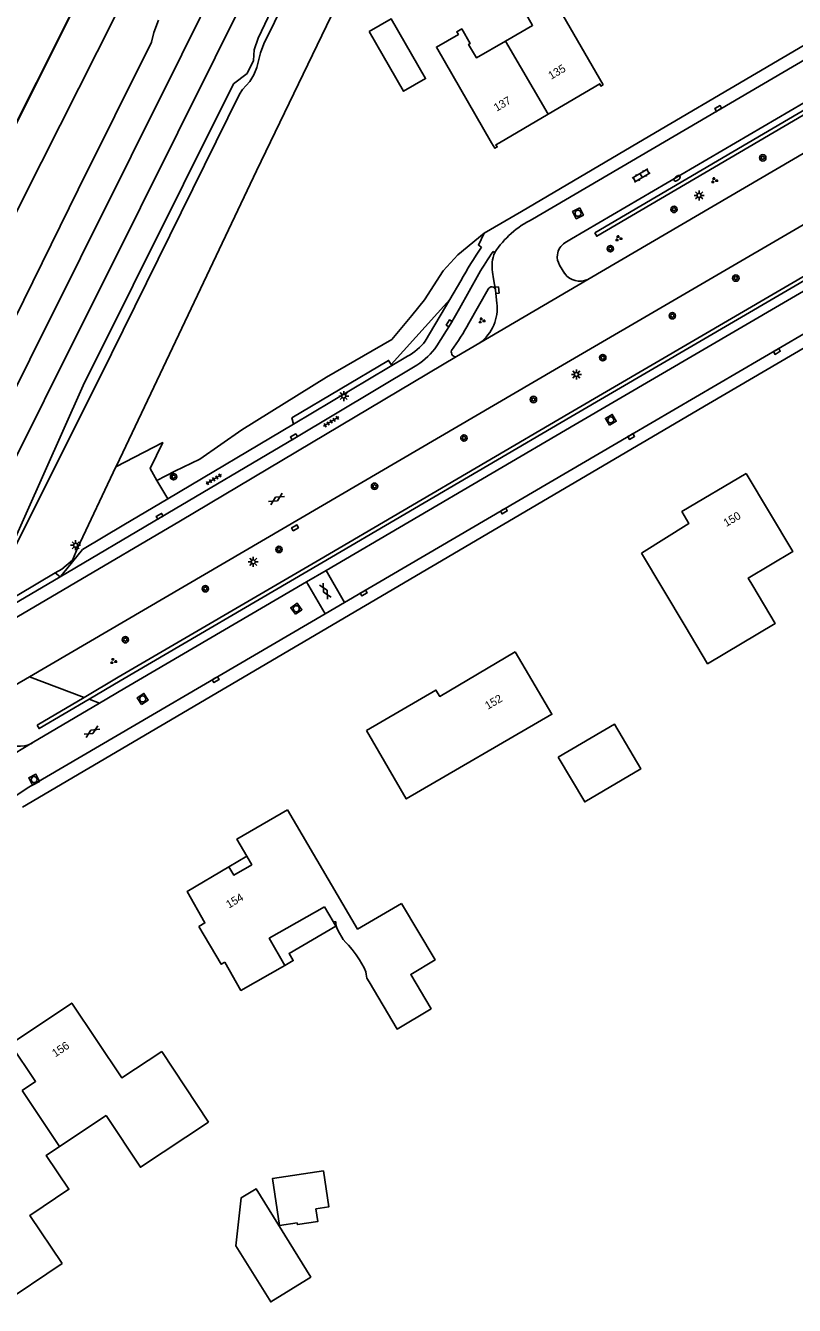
# Model space of a CAD drawing. Extents: x 135999 to 138000, y 396000 to 398501.
# Drawn here: x 136091.1 to 136187.2, y 397354.7 to 397514.6 of the extents above; entities that cross this region are included whole.
import ezdxf

# ---------------------------------------------------------------- set-up
doc = ezdxf.new("R2010")
doc.units = 0
for name, color, linetype in [('gg-afsc-hekwerk', 7, 'Continuous'), ('gg-anno-huisnummerreeks BGT', 7, 'Continuous'), ('gg-aspt-spoorlijn', 7, 'Continuous'), ('gg-bbg-gedigitaliseerde bebouwing', 7, 'Continuous'), ('gg-bbg-gedigitaliseerde bijgebouw', 7, 'Continuous'), ('gg-bbg-hoofdgebouw', 7, 'Continuous'), ('gg-bbg-luifel en loopbrug', 7, 'Continuous'), ('gg-bbg-tussenscheiding', 7, 'Continuous'), ('gg-knt-bovenkant onderkant talud', 7, 'Continuous'), ('gg-knt-verharding', 7, 'Continuous'), ('gt-grn-bladgrens', 7, 'Continuous'), ('gt-grn-groengrens', 7, 'Continuous'), ('gt-grn-vlakafsluiter', 7, 'Continuous'), ('gt-symb-boom', 7, 'Continuous'), ('gt-symb-brandkraan', 7, 'Continuous'), ('gt-symb-gesloten verharding', 7, 'Continuous'), ('gt-symb-groenvak', 7, 'Continuous'), ('gt-symb-klinker verharding', 7, 'Continuous'), ('gt-symb-kolk', 7, 'Continuous'), ('gt-symb-lichtmast', 7, 'Continuous'), ('gt-symb-rioolschacht', 7, 'Continuous'), ('gt-symb-tegel verharding', 7, 'Continuous'), ('gx-grn-maaiveld', 7, 'Continuous')]:
    doc.layers.add(name, color=color, linetype=linetype)

# ---------------------------------------------------------------- blocks, each defined once
blk = doc.blocks.new('gt0-KOLK')
at = {"layer": 'gt-symb-kolk'}
blk.add_lwpolyline([(0, 0), (0.38, 0), (0.38, 0.4), (-0.38, 0.4), (-0.38, 0), (0, 0)], dxfattribs=at)
blk = doc.blocks.new('gt0-BOOM')
at = {"layer": 'gt-symb-boom'}
for radius in [0.4, 0.2]:
    blk.add_circle((0, 0), radius, dxfattribs=at)
blk = doc.blocks.new('gt0-GRVAK')
at = {"layer": 'gt-symb-groenvak'}
for p, q in [((-0.11, 0.19), (-0.23, 0.24)), ((-0.18, 0.15), (0.09, 0.15)), ((-0.09, 0.21), (-0.16, 0.32)), ((-0.05, 0.21), (-0.05, 0.39)), ((0, 0.21), (0.06, 0.32)), ((0.02, 0.19), (0.13, 0.24)), ((0.26, -0.05), (0.2, 0.06)), ((0.3, -0.05), (0.3, 0.13)), ((0.35, -0.05), (0.41, 0.06)), ((-0.24, -0.23), (-0.36, -0.18)), ((-0.32, -0.26), (-0.05, -0.26)), ((-0.23, -0.21), (-0.29, -0.1)), ((-0.18, -0.2), (-0.18, -0.02)), ((-0.14, -0.21), (-0.07, -0.1)), ((-0.12, -0.23), (0, -0.18)), ((0.24, -0.07), (0.12, -0.02)), ((0.17, -0.11), (0.44, -0.11)), ((0.37, -0.07), (0.49, -0.02))]:
    blk.add_line(p, q, dxfattribs=at)
blk = doc.blocks.new('gt0-LMAST')
at = {"layer": 'gt-symb-lichtmast'}
for p, q in [((-0.18, 0.17), (-0.45, 0.44)), ((-0.01, 0.25), (-0.01, 0.62)), ((0.17, 0.17), (0.44, 0.44)), ((-0.26, 0), (-0.63, 0)), ((-0.18, -0.18), (-0.45, -0.45)), ((-0.01, -0.25), (-0.01, -0.63)), ((0.44, -0.45), (0.17, -0.18)), ((0.24, 0), (0.62, 0))]:
    blk.add_line(p, q, dxfattribs=at)
blk.add_circle((-0.01, 0), 0.25, dxfattribs=at)
blk = doc.blocks.new('gt0-TEG1')
at = {"layer": 'gt-symb-tegel verharding'}
for p, q in [((-1.12, 0), (1.13, 0)), ((-0.9, -0.25), (-0.9, 0.25)), ((-0.45, -0.25), (-0.45, 0.25)), ((0, -0.25), (0, 0.25)), ((0.45, -0.25), (0.45, 0.25)), ((0.9, -0.25), (0.9, 0.25))]:
    blk.add_line(p, q, dxfattribs=at)
blk = doc.blocks.new('gt0-GESVH1')
at = {"layer": 'gt-symb-gesloten verharding'}
for p, q in [((-0.99, -0.26), (0.01, 0.24)), ((0.01, -0.26), (-0.99, 0.24)), ((0.01, 0.24), (1.01, -0.26)), ((1.01, 0.24), (0.01, -0.26))]:
    blk.add_line(p, q, dxfattribs=at)
blk = doc.blocks.new('gt0-RS')
at = {"layer": 'gt-symb-rioolschacht'}
blk.add_lwpolyline([(-0.5, -0.5), (0.5, -0.5), (0.5, 0.5), (-0.5, 0.5)], close=True, dxfattribs=at)
blk.add_circle((0, 0), 0.375, dxfattribs=at)
blk = doc.blocks.new('gt0-KL1')
at = {"layer": 'gt-symb-klinker verharding'}
for p, q in [((-1.15, 0.3), (1.15, 0.3)), ((-1, -0.3), (-1, 0.3)), ((-0.5, 0.3), (-0.5, 0.45)), ((0, -0.3), (0, 0.3)), ((0.5, 0.3), (0.5, 0.45)), ((1, -0.3), (1, 0.3)), ((-1.15, -0.3), (1.15, -0.3)), ((-0.5, -0.45), (-0.5, -0.3)), ((0.5, -0.45), (0.5, -0.3))]:
    blk.add_line(p, q, dxfattribs=at)
blk = doc.blocks.new('gt0-BR')
at = {"layer": 'gt-symb-brandkraan'}
for centre, radius, start, end in [((-0.24, 0), 0.206, 107.5669, 252.4331), ((0.6, -2.66), 3, 106.892, 107.5669), ((0, -0.69), 0.938, 73.108, 106.892), ((-0.6, -2.66), 3, 72.4331, 73.108), ((0.24, 0), 0.206, 287.567, 72.4331), ((0.6, 2.66), 3, 252.4331, 253.108), ((0, 0.69), 0.938, 253.108, 286.8921), ((-0.6, 2.66), 3, 286.8921, 287.567)]:
    blk.add_arc(centre, radius, start, end, dxfattribs=at)

msp = doc.modelspace()

# ---------------------------------------------------------------- linework, layer by layer
at = {"layer": 'gg-afsc-hekwerk'}
msp.add_lwpolyline([(136206.22, 397710.07), (136203.26, 397711.27), (136196.98, 397710.23), (136193.86, 397709.75), (136188.71, 397699.53), (136178.32, 397679.53), (136172.59, 397668.77), (136160.48, 397645.24), (136132.77, 397588.81), (136102.14, 397526.87), (136090.23, 397502.97), (136088.59, 397499.81), (136086.91, 397496.59), (136075.23, 397472.87), (136076.15, 397472.41)], dxfattribs=at)
at = {"layer": 'gg-aspt-spoorlijn'}
for points in [[(136075.9, 397441.46), (136078.9, 397447.5), (136110.62, 397511), (136126.65, 397543.4), (136168.42, 397626.98), (136182.98, 397656.49), (136206.97, 397704.32), (136208.88, 397708.17)], [(136081.38, 397443.76), (136105.46, 397491.91), (136152.12, 397585.65), (136171.93, 397625.02), (136194.83, 397671.15), (136212.4, 397706.41)]]:
    msp.add_lwpolyline(points, dxfattribs=at)
at = {"layer": 'gg-bbg-gedigitaliseerde bebouwing'}
for p, q in [((136168.08, 397448.74), (136173.51, 397439.61)), ((136128.43, 397404.54), (136129.52, 397402.71)), ((136108.12, 397386.48), (136113.95, 397377.65)), ((136101.15, 397378.49), (136095.33, 397374.6)), ((136087.83, 397354.75), (136095.65, 397359.97))]:
    msp.add_line(p, q, dxfattribs=at)
for points in [[(136163.28, 397507.24), (136155.93, 397519.94), (136152.95, 397518.22), (136152.8, 397518.48), (136152.19, 397518.14), (136153.29, 397516.23), (136153.48, 397516.34), (136154.45, 397514.65), (136151.05, 397512.69)], [(136151.05, 397512.69), (136147.42, 397510.61), (136146.46, 397512.27), (136146.64, 397512.38), (136145.59, 397514.21), (136144.97, 397513.86), (136145.17, 397513.52), (136142.42, 397511.95), (136149.33, 397500)], [(136181.98, 397444.66), (136181.41, 397445.61), (136186.97, 397448.93), (136181.16, 397458.69)], [(136181.98, 397444.66), (136184.79, 397439.95), (136176.33, 397434.9), (136173.51, 397439.61)], [(136152.29, 397436.4), (136156.86, 397428.61), (136138.65, 397418.02), (136133.69, 397426.58)], [(136128.43, 397404.54), (136121.53, 397400.61), (136123.47, 397397.21)], [(136134.01, 397395.17), (136137.52, 397389.27), (136141.77, 397391.8), (136139.22, 397396.09), (136142.26, 397397.9), (136138.08, 397404.94)], [(136115.98, 397397.62), (136115.53, 397397.36), (136112.74, 397402.09)], [(136129.52, 397402.71), (136129.86, 397402.66), (136129.86, 397402.45), (136129.9, 397402.15), (136129.97, 397401.9), (136130.15, 397401.54), (136130.78, 397400.45), (136131.11, 397400.1), (136131.45, 397399.75), (136131.91, 397399.2), (136132.42, 397398.53), (136132.81, 397397.94), (136133.42, 397396.91), (136133.59, 397396.43), (136133.66, 397396.12), (136133.75, 397395.65), (136134.01, 397395.17)], [(136123.47, 397397.21), (136117.99, 397394.09), (136115.98, 397397.62)], [(136113.95, 397377.65), (136105.43, 397372.01), (136101.15, 397378.49)], [(136095.33, 397374.6), (136093.67, 397373.49), (136096.5, 397369.26), (136091.61, 397365.98), (136095.65, 397359.97)]]:
    msp.add_lwpolyline(points, dxfattribs=at)
at = {"layer": 'gg-bbg-gedigitaliseerde bijgebouw'}
for points in [[(136134.04, 397513.88), (136136.78, 397515.46), (136141.07, 397508.01), (136138.32, 397506.43), (136134.04, 397513.88)], [(136157.66, 397423.23), (136160.96, 397417.64), (136167.98, 397421.78), (136164.68, 397427.37), (136157.66, 397423.23)], [(136128.3, 397371.55), (136121.93, 397370.6), (136122.8, 397364.73), (136125.02, 397365.06), (136125.06, 397364.85), (136127.6, 397365.22), (136127.36, 397366.81), (136128.97, 397367.05), (136128.3, 397371.55)], [(136117.38, 397362.21), (136118.04, 397368.19), (136119.91, 397369.31), (136126.73, 397358.29), (136121.73, 397355.19), (136117.38, 397362.21)]]:
    msp.add_lwpolyline(points, dxfattribs=at)
at = {"layer": 'gg-bbg-hoofdgebouw'}
msp.add_line((136150.3, 397500), (136156.39, 397503.58), dxfattribs=at)
for points in [[(136156.39, 397503.58), (136162.84, 397507.36), (136162.98, 397507.08), (136163.28, 397507.24)], [(136149.33, 397500), (136149.74, 397499.3), (136150.04, 397499.48), (136149.87, 397499.75), (136150.3, 397500)], [(136181.16, 397458.69), (136173.12, 397453.91), (136174, 397452.43), (136168.08, 397448.74)], [(136133.69, 397426.58), (136142.37, 397431.61), (136142.84, 397430.82), (136152.29, 397436.4)], [(136123.82, 397416.65), (136117.5, 397413), (136118.73, 397410.87)], [(136138.08, 397404.94), (136132.57, 397401.77), (136123.82, 397416.65)], [(136116.49, 397409.54), (136117.09, 397408.5), (136119.35, 397409.8), (136118.73, 397410.87)], [(136116.49, 397409.54), (136111.27, 397406.44), (136113.5, 397402.53), (136112.74, 397402.09)], [(136090.67, 397381.61), (136092.33, 397382.73), (136089.21, 397387.4), (136096.86, 397392.51), (136103.12, 397383.16), (136108.12, 397386.48)]]:
    msp.add_lwpolyline(points, dxfattribs=at)
at = {"layer": 'gg-bbg-luifel en loopbrug'}
msp.add_line((136116.49, 397409.54), (136118.73, 397410.87), dxfattribs=at)
msp.add_lwpolyline([(136123.47, 397397.21), (136124.54, 397397.82), (136124.01, 397398.73), (136129.87, 397402.11), (136129.52, 397402.71)], dxfattribs=at)
at = {"layer": 'gg-bbg-tussenscheiding'}
for p, q in [((136151.05, 397512.69), (136156.39, 397503.58)), ((136090.67, 397381.61), (136095.33, 397374.6))]:
    msp.add_line(p, q, dxfattribs=at)
at = {"layer": 'gg-knt-bovenkant onderkant talud'}
msp.add_lwpolyline([(136096.95, 397447.84), (136097.55, 397449.34), (136102.37, 397459.52)], dxfattribs=at)
at = {"layer": 'gg-knt-verharding'}
for p, q in [((136149.72, 397486.27), (136149.52, 397486.41)), ((136158.47, 397483.64), (136157.83, 397484.71)), ((136144.12, 397480.42), (136145.5, 397482.75)), ((136147.85, 397475), (136161.34, 397482.9)), ((136141.02, 397475.22), (136144.12, 397480.42)), ((136146.49, 397477.45), (136148.89, 397481.71)), ((136149.99, 397479.97), (136149.82, 397481.59)), ((136144.96, 397473.29), (136147.85, 397475)), ((136138.83, 397473.34), (136124.55, 397464.85)), ((136124.55, 397464.85), (136108.84, 397455.51)), ((136094.79, 397446.25), (136095.62, 397446.74)), ((136095.62, 397446.74), (136096.95, 397447.84)), ((136095.69, 397446.12), (136095.42, 397445.78)), ((136128.65, 397446.57), (136126.2, 397445.14)), ((136126.2, 397445.14), (136128.51, 397441.15)), ((136130.94, 397442.57), (136128.65, 397446.57)), ((136130.94, 397442.57), (136128.51, 397441.15)), ((136086.85, 397430.54), (136091.55, 397433.29)), ((136100.33, 397429.99), (136091.89, 397425.01))]:
    msp.add_line(p, q, dxfattribs=at)
for points in [[(136154.43, 397490.43), (136206.35, 397520.89), (136227.04, 397533), (136240.35, 397540.82), (136259.46, 397552.07), (136276.59, 397562.11), (136287.32, 397568.41), (136289.03, 397569.4)], [(136289.47, 397564.17), (136255.15, 397544.03), (136190.06, 397506), (136159.32, 397487.99), (136158.49, 397487.49)], [(136161.34, 397482.9), (136241.87, 397530.06), (136295.03, 397560.71), (136295.87, 397561.3)], [(136091.55, 397433.29), (136157.18, 397471.63), (136241.16, 397520.6), (136300.13, 397555.2)], [(136302.91, 397548.5), (136285.12, 397538.12), (136201.43, 397489.11), (136159.77, 397464.79), (136128.65, 397446.57)], [(136307.8, 397544.23), (136276.31, 397525.85), (136176.45, 397467.39), (136090.68, 397416.98)], [(136130.94, 397442.57), (136166.67, 397463.47), (136201.88, 397484.04), (136272.38, 397525.34), (136305.21, 397544.51)], [(136196.49, 397516.94), (136168.4, 397500.43), (136153.05, 397491.42), (136148.38, 397488.72)], [(136148.38, 397488.72), (136147.69, 397487.22), (136148.08, 397486.96)], [(136142.48, 397474.62), (136144.2, 397477.33), (136144.81, 397478.41), (136145.3, 397479.28), (136147.74, 397483.63)], [(136149.45, 397483.84), (136149.57, 397483.01), (136149.82, 397481.59)], [(136144.96, 397473.29), (136110.46, 397452.75), (136082.67, 397436.44)], [(136139.98, 397472.21), (136124.72, 397463.09), (136107.95, 397453.16), (136095.42, 397445.78)], [(136108.84, 397455.51), (136103.38, 397452.26), (136098.21, 397449.2), (136095.69, 397446.12)], [(136095.42, 397445.78), (136089.53, 397442.32), (136084, 397439.1)], [(136084.66, 397440.42), (136085.44, 397440.71), (136094.79, 397446.25)], [(136126.2, 397445.14), (136103.48, 397431.84), (136100.33, 397429.99)], [(136128.51, 397441.15), (136091.47, 397419.47), (136089.79, 397418.36)], [(136086.89, 397421.92), (136088.61, 397423.04), (136091.89, 397425.01)]]:
    msp.add_lwpolyline(points, dxfattribs=at)
for centre, radius, start, end in [((136159.61, 397479.83), 11.81, 116.0465, 146.9071), ((136184.54, 397461.82), 44.3, 145.4133, 151.8034), ((136159.56, 397485.76), 2.02, 121.6775, 172.8362), ((136187.09, 397460.43), 45.68, 145.335, 149.4664), ((136154.02, 397484.57), 4.63, 158.4245, 189.1686), ((136159.55, 397485.77), 2.02, 172.8809, 211.4406), ((136160.37, 397485.07), 2.37, 216.823, 294.1108), ((136149.34, 397481.49), 0.497, 11.5836, 154.0001), ((136144.68, 397479.31), 5.35, 306.3606, 7.0975), ((136115.31, 397494.7), 35.63, 324.5449, 331.0477), ((136135.93, 397478.95), 6.31, 297.3096, 323.7941), ((136135.56, 397479.31), 8.36, 301.9139, 325.9199), ((136144.83, 397473.81), 0.541, 156.2874, 284.4686), ((136090.39, 397427.59), 2.99, 223.7791, 300.1932)]:
    msp.add_arc(centre, radius, start, end, dxfattribs=at)
at = {"layer": 'gt-grn-bladgrens'}
for p, q in [((136107.1, 397513.77), (136107.7, 397515.32)), ((136097.64, 397494.15), (136106.82, 397512.56)), ((136106.82, 397512.56), (136107.1, 397513.77)), ((136085.15, 397468.75), (136097.64, 397494.15))]:
    msp.add_line(p, q, dxfattribs=at)
at = {"layer": 'gt-grn-groengrens'}
for p, q in [((136108.84, 397455.51), (136107.5, 397457.81)), ((136091.55, 397433.29), (136098.41, 397430.71)), ((136098.41, 397430.71), (136092.51, 397427.24)), ((136099.01, 397430.48), (136100.33, 397429.99))]:
    msp.add_line(p, q, dxfattribs=at)
for points in [[(136289.46, 397563.39), (136289.71, 397562.96), (136162.46, 397488.32), (136162.21, 397488.75)], [(136289.46, 397563.39), (136181.39, 397500), (136162.21, 397488.75)], [(136301.08, 397549.28), (136284.32, 397539.51), (136200.63, 397490.5), (136158.97, 397466.18), (136127.84, 397447.95)], [(136301.08, 397549.28), (136301.33, 397548.85), (136284.57, 397539.07), (136200.88, 397490.07), (136159.22, 397465.74), (136128.09, 397447.52)], [(136148.38, 397488.72), (136145.11, 397486.01), (136143.27, 397483.99), (136140.96, 397480.36), (136139.34, 397478.42), (136136.86, 397475.43), (136128.7, 397470.69), (136118.13, 397464.14), (136112.84, 397460.46), (136109.72, 397458.98), (136107.5, 397457.81)], [(136124.55, 397464.85), (136124.37, 397465.65), (136136.46, 397472.8), (136136.77, 397472.31), (136144.12, 397480.42)], [(136107.5, 397457.81), (136106.64, 397459.3), (136108.23, 397462.54), (136102.37, 397459.52)], [(136127.84, 397447.95), (136102.67, 397433.22), (136098.41, 397430.71)], [(136128.09, 397447.52), (136102.92, 397432.79), (136099.01, 397430.48)], [(136099.01, 397430.48), (136092.77, 397426.81), (136092.51, 397427.24)]]:
    msp.add_lwpolyline(points, dxfattribs=at)
at = {"layer": 'gt-grn-vlakafsluiter'}
msp.add_line((136094.79, 397446.25), (136095.42, 397445.78), dxfattribs=at)
msp.add_lwpolyline([(136178.88, 397680.61), (136166.53, 397657.01), (136160.48, 397645.24), (136147.38, 397618.57), (136132.77, 397588.81), (136103.22, 397529.06), (136086.99, 397496.75)], dxfattribs=at)
at = {"layer": 'gx-grn-maaiveld'}
msp.add_line((136119.96, 397496.47), (136138.35, 397534.64), dxfattribs=at)
for points in [[(136079.12, 397470.95), (136089.3, 397490.11), (136093.09, 397497.58), (136116.32, 397543.68), (136148.79, 397608.63), (136171.6, 397654), (136190.78, 397691.87), (136195.5, 397701), (136198.41, 397705.89), (136200.96, 397709.86), (136201.44, 397710.49), (136201.81, 397710.81)], [(136088.62, 397447.99), (136088.69, 397448.1), (136089.21, 397448.33), (136101.82, 397473.61), (136117.8, 397506.05), (136118.2, 397506.65), (136119.09, 397507.65), (136119.61, 397508.49), (136120, 397509.39), (136120.44, 397511.21), (136120.86, 397512.36), (136140.9, 397553.07)], [(136088.62, 397447.99), (136098.28, 397469.68), (136117.08, 397507.35), (136118.77, 397508.66), (136119.55, 397510.29), (136119.66, 397511.62), (136120.15, 397513.06), (136124.63, 397522.56)], [(136102.37, 397459.52), (136102.43, 397459.65), (136119.96, 397496.47)]]:
    msp.add_lwpolyline(points, dxfattribs=at)

# ---------------------------------------------------------------- block references
at = {"layer": 'gt-symb-boom'}
for p in [(136183.22, 397498.11), (136172.13, 397491.67), (136164.17, 397486.76), (136179.85, 397483.09), (136171.92, 397478.38), (136163.22, 397473.15), (136154.56, 397467.92), (136145.87, 397463.11), (136109.58, 397458.28), (136134.7, 397457.08), (136122.75, 397449.19), (136113.55, 397444.28)]:
    msp.add_blockref('gt0-BOOM', p, dxfattribs=at)
at = {"layer": 'gt-symb-boom', "rotation": 90}
msp.add_blockref('gt0-BOOM', (136103.55, 397437.91), dxfattribs=at)
at = {"layer": 'gt-symb-brandkraan', "rotation": -143.4967170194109}
msp.add_blockref('gt0-BR', (136172.51, 397495.55), dxfattribs=at)
at = {"layer": 'gt-symb-gesloten verharding'}
for p, rotation in [((136122.43, 397455.49), 31.46487302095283), ((136128.55, 397443.99), -59.87139976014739), ((136099.36, 397426.42), 31.052160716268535)]:
    msp.add_blockref('gt0-GESVH1', p, dxfattribs=dict(at, rotation=rotation))
at = {"layer": 'gt-symb-groenvak'}
for p in [(136177.16, 397495.29), (136165.18, 397488.04), (136148.08, 397477.78), (136102.04, 397435.23)]:
    msp.add_blockref('gt0-GRVAK', p, dxfattribs=at)
at = {"layer": 'gt-symb-klinker verharding', "rotation": 30.718190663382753}
msp.add_blockref('gt0-KL1', (136168.02, 397495.9), dxfattribs=at)
at = {"layer": 'gt-symb-kolk'}
for p, rotation in [((136177.75, 397504.11), 30.384237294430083), ((136149.83, 397481.56), -84.2609015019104), ((136144.2, 397477.33), 57.66062292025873), ((136184.88, 397474.1), -149.7435628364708), ((136124.72, 397463.09), 30.66892664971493), ((136166.67, 397463.47), -149.74356283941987), ((136107.95, 397453.16), 30.46264004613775), ((136150.76, 397454.16), -149.66519417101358), ((136124.66, 397452.06), -149.7435628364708), ((136133.24, 397443.91), -149.66519417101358), ((136114.75, 397433.1), -149.66519416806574)]:
    msp.add_blockref('gt0-KOLK', p, dxfattribs=dict(at, rotation=rotation))
at = {"layer": 'gt-symb-lichtmast'}
for p in [(136175.27, 397493.42), (136159.93, 397471.05), (136130.85, 397468.35), (136097.34, 397449.71), (136119.54, 397447.64)]:
    msp.add_blockref('gt0-LMAST', p, dxfattribs=at)
at = {"layer": 'gt-symb-rioolschacht'}
for p, rotation in [((136160.13, 397491.18), -153.05041916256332), ((136164.23, 397465.38), 30.384237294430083), ((136124.92, 397441.78), 35.15153964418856), ((136105.72, 397430.51), 33.086307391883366), ((136092.15, 397420.43), 26.43687291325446)]:
    msp.add_blockref('gt0-RS', p, dxfattribs=dict(at, rotation=rotation))
at = {"layer": 'gt-symb-tegel verharding', "rotation": 31.33720572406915}
for p in [(136129.28, 397465.16), (136114.59, 397457.95)]:
    msp.add_blockref('gt0-TEG1', p, dxfattribs=at)

# ---------------------------------------------------------------- texts
at = {"layer": 'gg-anno-huisnummerreeks BGT'}
for s, rotation, p in [('135', 30.4, (136156.77, 397507.86)), ('137', 30.4, (136149.96, 397503.86)), ('150', 30.7, (136178.67, 397451.98)), ('152', 30.5, (136148.86, 397429.15)), ('154', 30.7, (136116.5, 397404.31)), ('156', 33.8, (136094.8, 397385.72))]:
    msp.add_text(s, height=1, rotation=rotation, dxfattribs=at).set_placement(p)

doc.saveas('drawing.dxf')
